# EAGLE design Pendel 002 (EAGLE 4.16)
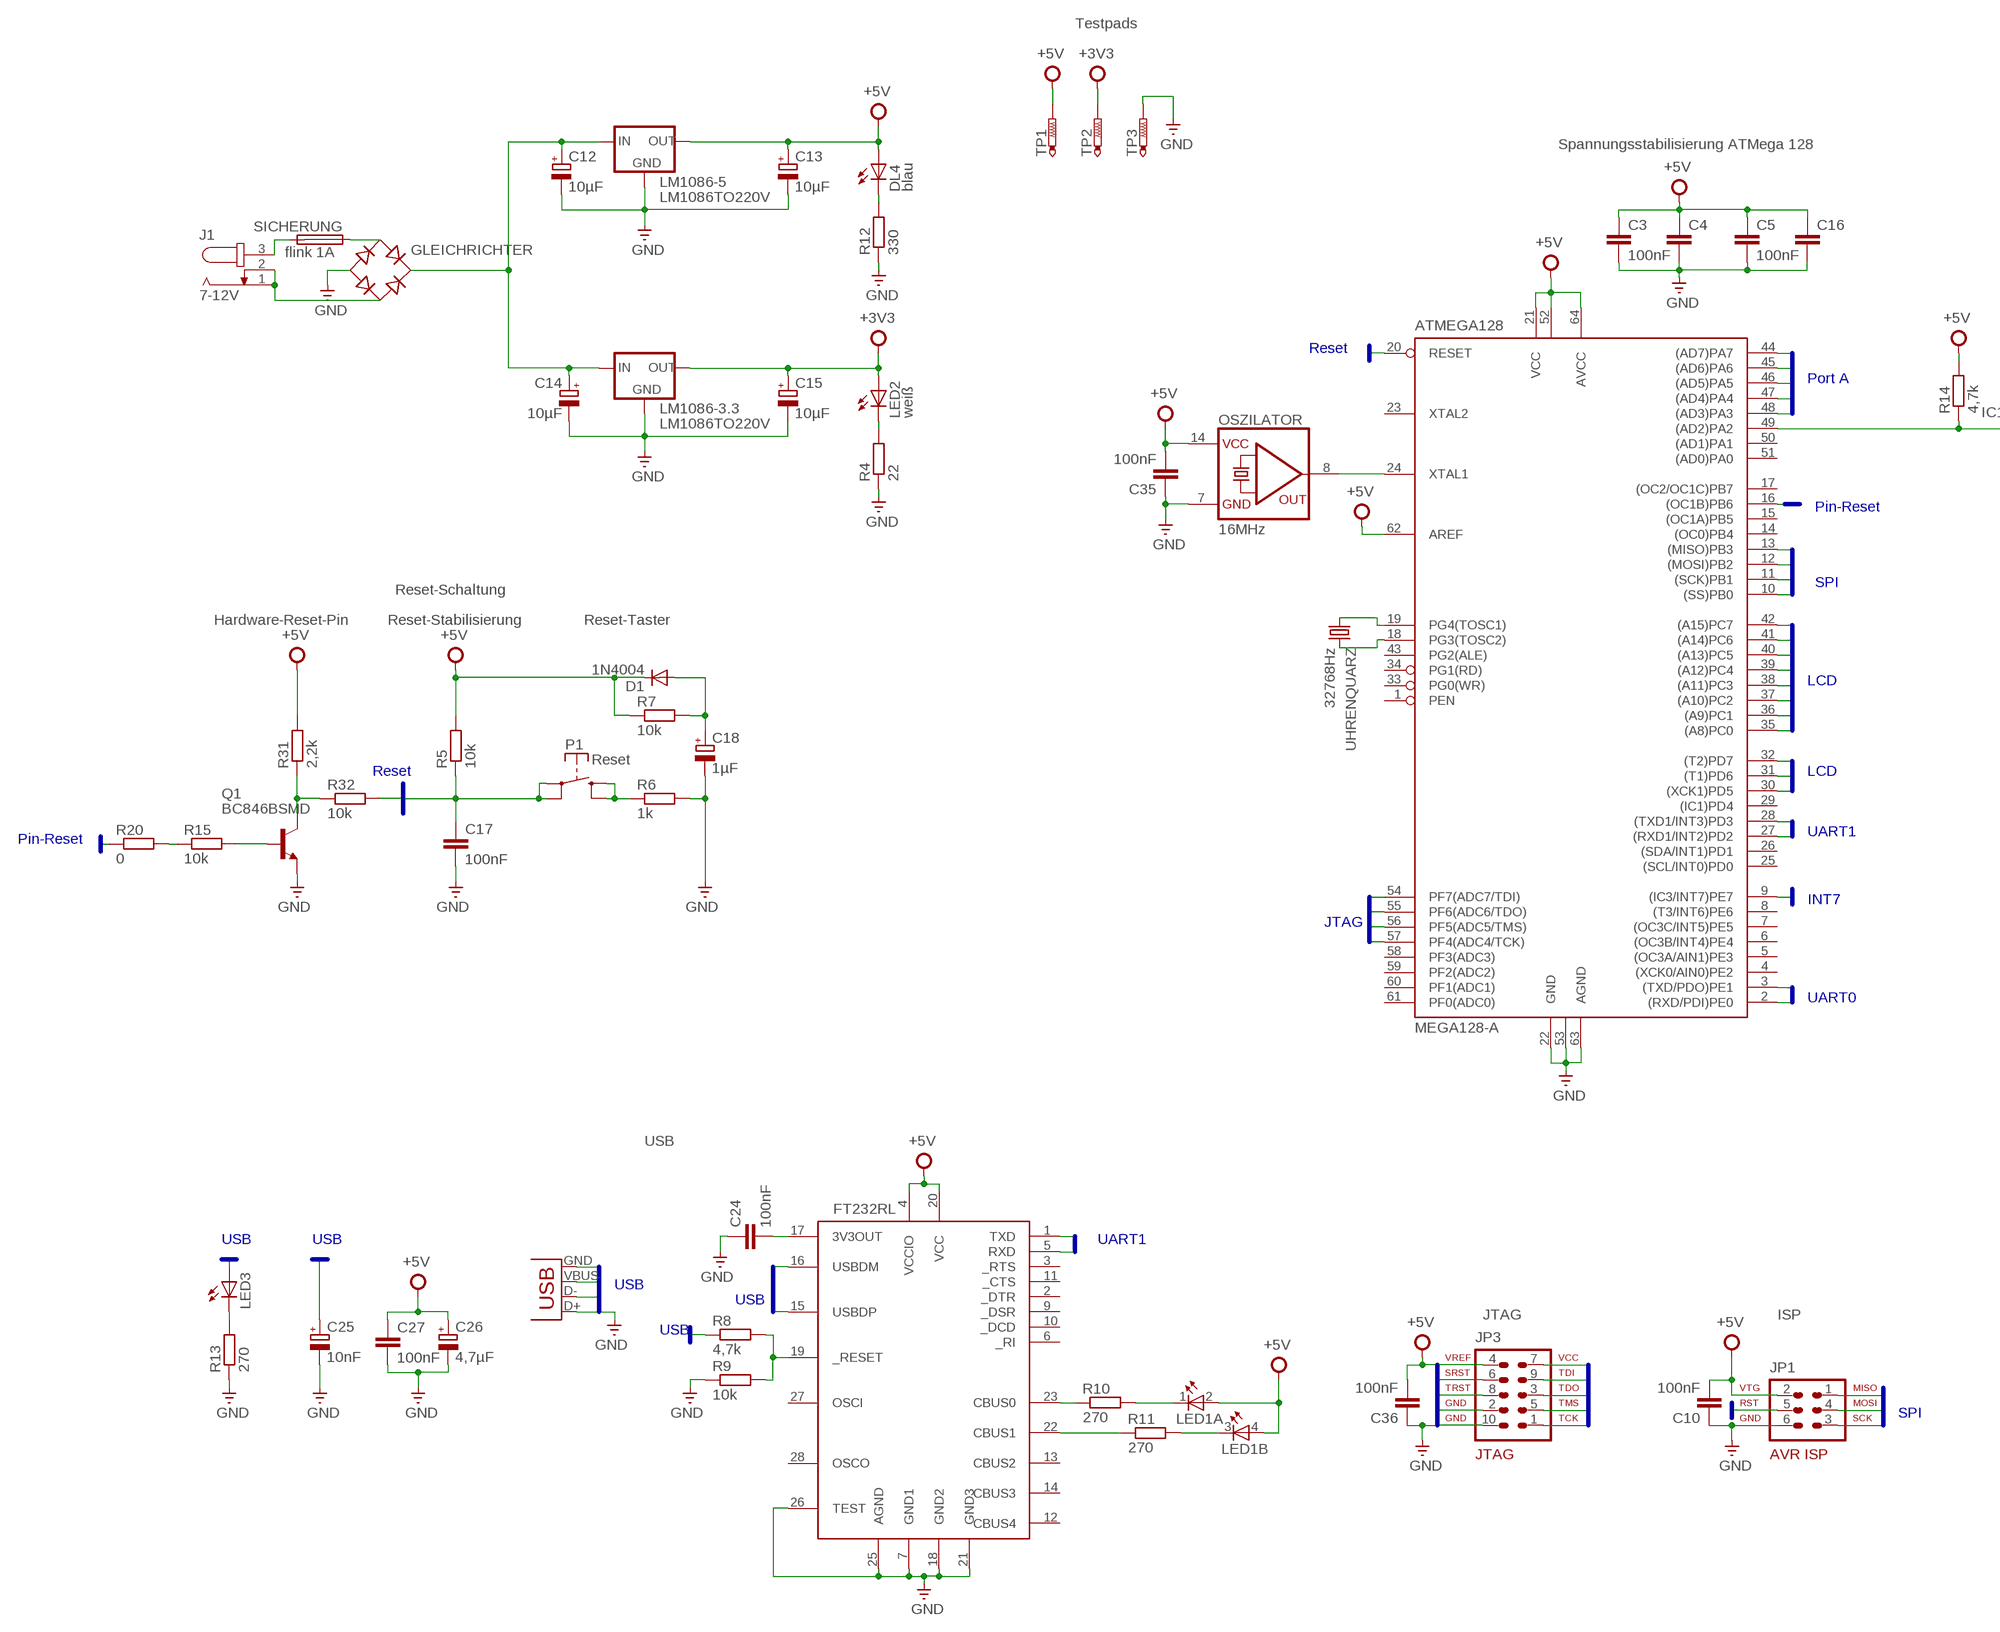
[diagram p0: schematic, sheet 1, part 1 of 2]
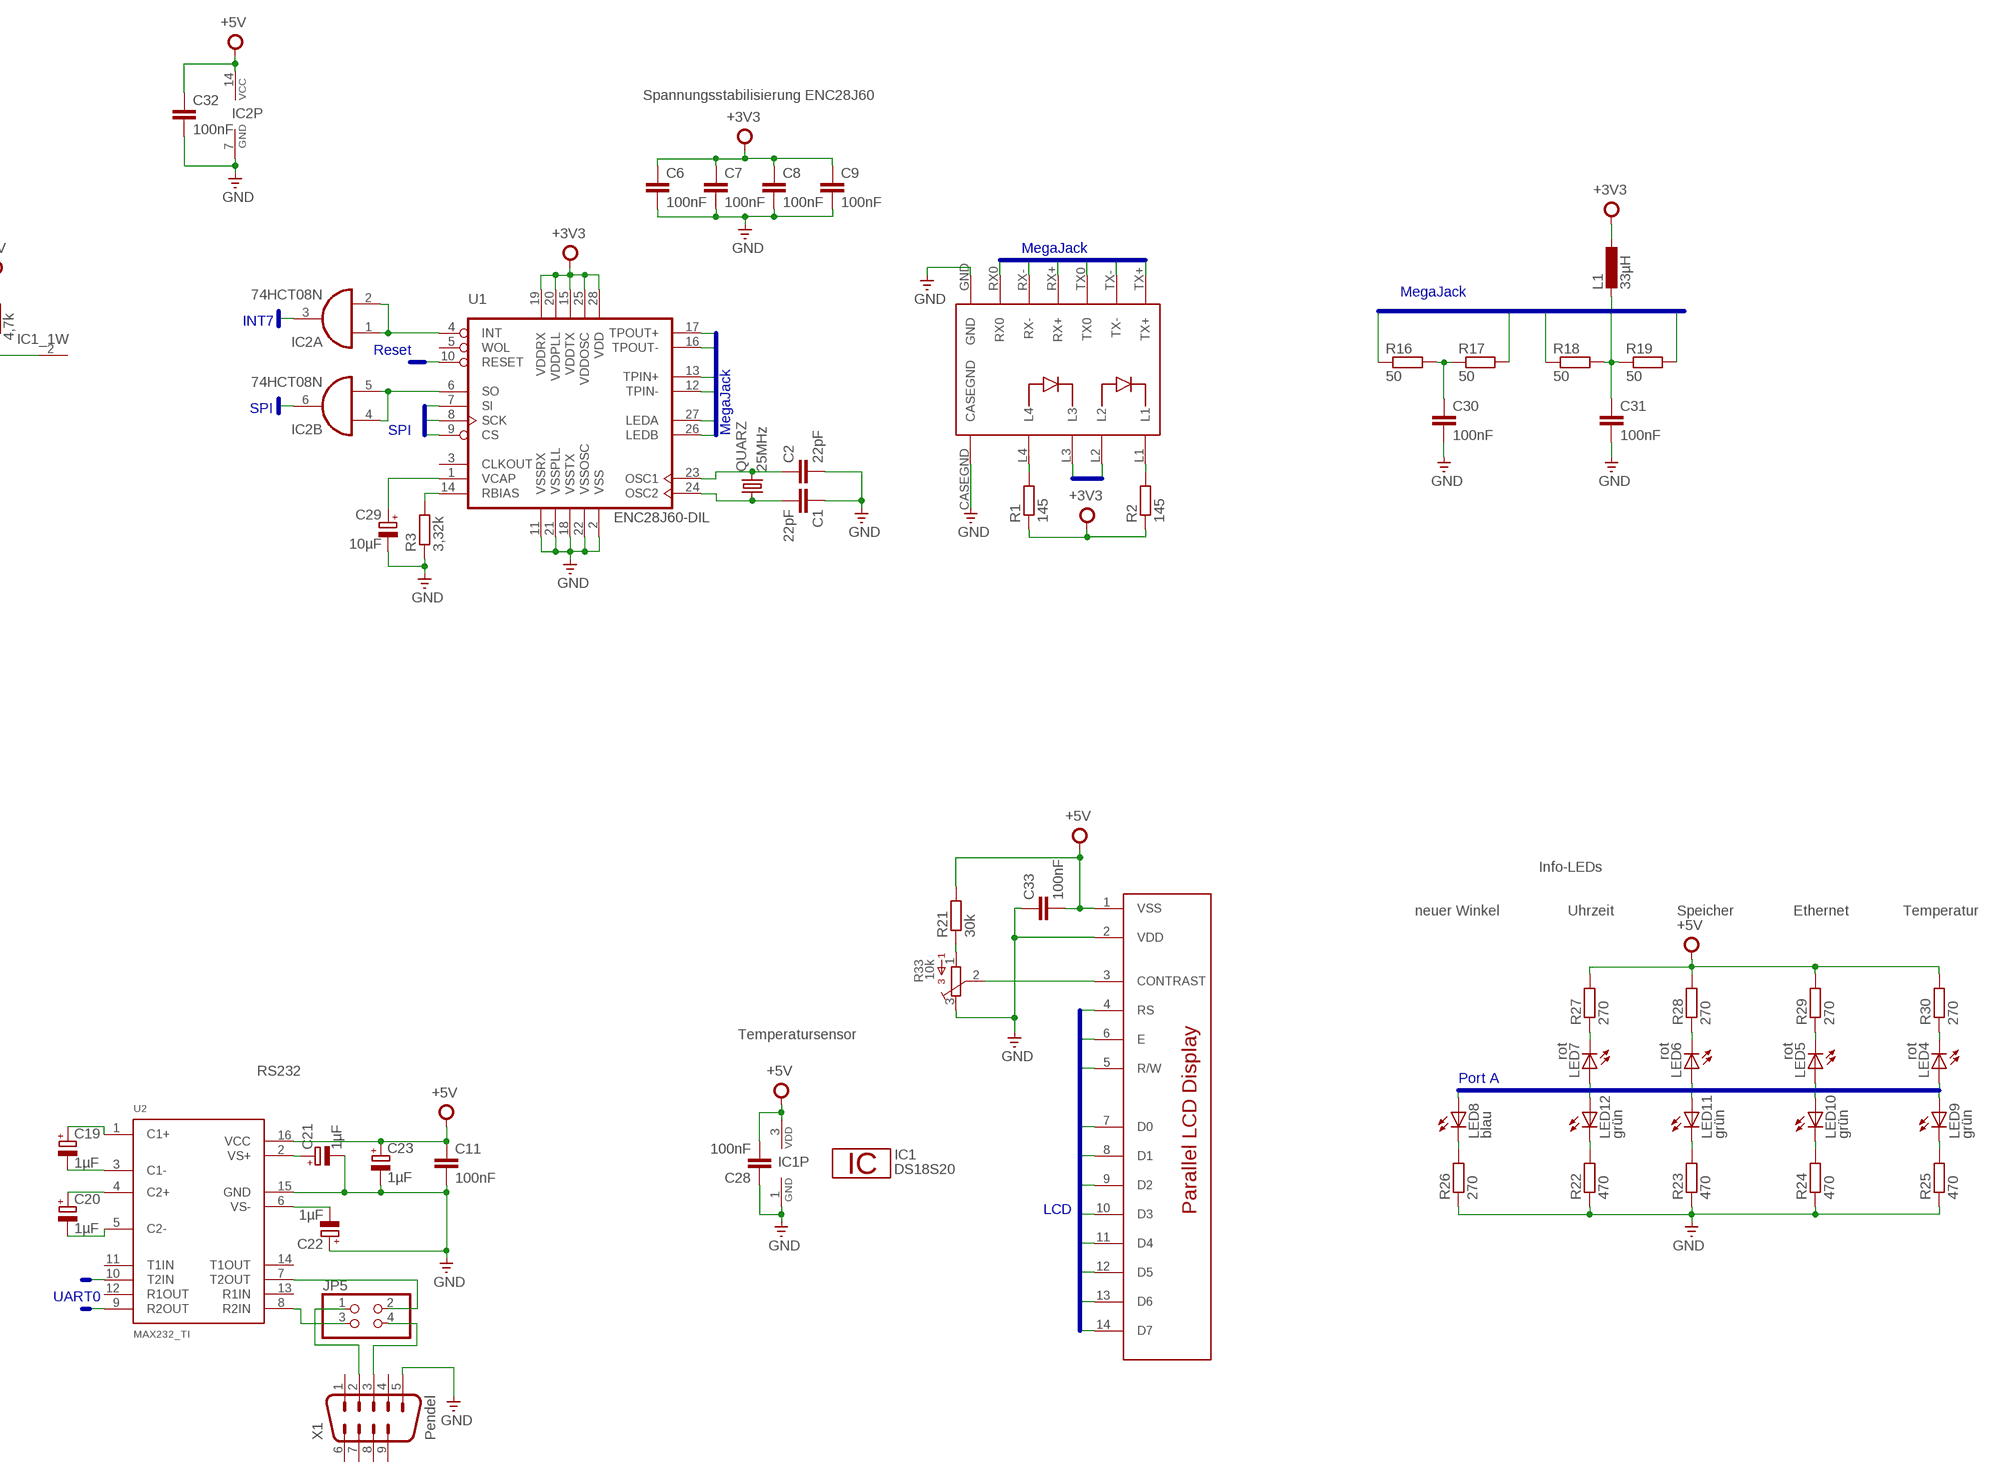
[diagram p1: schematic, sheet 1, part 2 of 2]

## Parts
ATMEGA128  MEGA128-A  [TQFP64-AEB]
C1  22pF  C-EUC1206  [C1206]
C2  22pF  C-EUC1206  [C1206]
C3  100nF  C-EUC0603  [C0603]
C4  C-EUC0603  [C0603]
C5  100nF  C-EUC0603  [C0603]
C6  100nF  C-EUC1206  [C1206]
C7  100nF  C-EUC1206  [C1206]
C8  100nF  C-EUC1206  [C1206]
C9  100nF  C-EUC1206  [C1206]
C10  100nF  C-EUC0805  [C0805]
C11  100nF  C-EUC1206  [C1206]
C12  10µF  CPOL-EUE2.5-6  [E2,5-6]
C13  10µF  CPOL-EUE2.5-6  [E2,5-6]
C14  10µF  CPOL-EUE2.5-6  [E2,5-6]
C15  10µF  CPOL-EUE2.5-6  [E2,5-6]
C16  C-EUC0603  [C0603]
C17  100nF  C-EUC1206  [C1206]
C18  1µF  CPOL-EUE2.5-6  [E2,5-6]
C19  1µF  CPOL-EUE2.5-6  [E2,5-6]
C20  1µF  CPOL-EUE2.5-6  [E2,5-6]
C21  1µF  CPOL-EUE2.5-6  [E2,5-6]
C22  1µF  CPOL-EUE2.5-6  [E2,5-6]
C23  1µF  CPOL-EUE2.5-6  [E2,5-6]
C24  100nF  C-EUC1206  [C1206]
C25  10nF  CPOL-EUE2.5-6  [E2,5-6]
C26  4,7µF  CPOL-EUE2.5-6  [E2,5-6]
C27  100nF  C-EUC1206  [C1206]
C28  100nF  C-EUC1206  [C1206]
C29  10µF  CPOL-EUE2.5-6  [E2,5-6]
C30  100nF  C-EUC1206  [C1206]
C31  100nF  C-EUC1206  [C1206]
C32  100nF  C-EUC1206  [C1206]
C33  100nF  C-EUC1206  [C1206]
C35  100nF  C-EUC1206  [C1206]
C36  100nF  C-EUC1206  [C1206]
D1  1N4004  [DO41-10]
DL4  blau  LEDCHIPLED_0603  [CHIPLED_0603]
FT232RL  FT232RL  [SSOP28DB]
GLEICHRICHTER  RB1A  [RB1A]
IC1  DS18S20  [TO92-]
IC2  74HCT08N  [DIL14]
J1  7-12V  JACK-PLUG0  [SPC4077]
JP1  AVR-ISP-6  [AVR-ISP-6]
JP3  AVR-JTAG-10  [AVR-JTAG-10]
JP5  PINHD-2X2_2.54  [2X02]
L1  33µH  L-EU2200-15.24  [2200-15.24]
LED1  TOPLED-2-/  [P-LCC-4/2]
LED2  weiß  LED5MM  [LED5MM]
LED3  LEDP-LCC-2  [P-LCC-2]
LED4  rot  LED5MM  [LED5MM]
LED5  rot  LED5MM  [LED5MM]
LED6  rot  LED5MM  [LED5MM]
LED7  rot  LED5MM  [LED5MM]
LED8  blau  LED5MM  [LED5MM]
LED9  grün  LED3MM  [LED3MM]
LED10  grün  LED3MM  [LED3MM]
LED11  grün  LED3MM  [LED3MM]
LED12  grün  LED3MM  [LED3MM]
LM1086-3.3  LM1086TO220V  [TO220S]
LM1086-5  LM1086TO220V  [TO220S]
OSZILATOR  16MHz  QG5860  [DIL14S]
P1  Reset  FSMCD  [FSMCD]
Q1  BC846BSMD  [SOT23]
QUARZ  25MHz  CRYTALHC49S  [HC49/S]
R1  145  R-EU_R1206  [R1206]
R2  145  R-EU_R1206  [R1206]
R3  3,32k  R-EU_R1206  [R1206]
R4  22  R-EU_R1206  [R1206]
R5  10k  R-EU_R1206  [R1206]
R6  1k  R-EU_R1206  [R1206]
R7  10k  R-EU_R1206  [R1206]
R8  4,7k  R-EU_R1206  [R1206]
R9  10k  R-EU_R1206  [R1206]
R10  270  R-EU_R1206  [R1206]
R11  270  R-EU_R1206  [R1206]
R12  330  R-EU_R1206  [R1206]
R13  270  R-EU_R1206  [R1206]
R14  4,7k  R-EU_R1206  [R1206]
R15  10k  R-EU_R1206  [R1206]
R16  50  R-EU_R1206  [R1206]
R17  50  R-EU_R1206  [R1206]
R18  50  R-EU_R1206  [R1206]
R19  50  R-EU_R1206  [R1206]
R20  0  R-EU_R1206  [R1206]
R21  30k  R-EU_R1206  [R1206]
R22  470  R-EU_R1206  [R1206]
R23  470  R-EU_R1206  [R1206]
R24  470  R-EU_R1206  [R1206]
R25  470  R-EU_R1206  [R1206]
R26  270  R-EU_R1206  [R1206]
R27  270  R-EU_R1206  [R1206]
R28  270  R-EU_R1206  [R1206]
R29  270  R-EU_R1206  [R1206]
R30  270  R-EU_R1206  [R1206]
R31  2,2k  R-EU_R1206  [R1206]
R32  10k  R-EU_R1206  [R1206]
R33  10k  3386-G  [3386G]
SICHERUNG  flink 1A  SH22,5A  [SH22,5A]
TP1  PTR1PAD1-13Y  [P1-13Y]
TP2  PTR1PAD1-13Y  [P1-13Y]
TP3  PTR1PAD1-13Y  [P1-13Y]
U1  ENC28J60-DIL  [DIL28-3]
U2  MAX232_TI  [DIL16]
U$2  PARALLEL_LCDDIP  [DIP_14]
U$3  1XRJ45_MM_JACK  [1XRJ45_MM_JACK]
UHRENQUARZ  32768Hz  CRYTALTC38H  [TC38H]
X1  Pendel  M09H  [M09H]
X2  USB-B-H  [USB-B-H]

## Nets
+3V3: C6.1 C7.1 C8.1 C9.1 C15.+ L1.1 LED2.A LM1086-3.3.2(OUT) R1.1 R2.1 TP2.1(TP) U1.15(VDDTX) U1.19(VDDRX) U1.20(VDDPLL) U1.25(VDDOSC) U1.28(VDD)
+5V: ATMEGA128.21(VCC) ATMEGA128.52(VCC1) ATMEGA128.62(AREF) ATMEGA128.64(AVCC) C3.1 C4.1 C5.1 C10.2 C11.1 C13.+ C16.1 C23.+ C26.+ C27.1 C28.2 C32.1 C33.2 C35.2 C36.2 D1.C DL4.A FT232RL.4(VCCIO) FT232RL.20(VCC) IC1.3 IC2.14(P:VCC) JP1.2 JP3.7 LED1.2(A:A) LED1.4(B:A) LM1086-5.2(OUT) OSZILATOR.14(VCC) R5.2 R7.1 R14.2 R21.2 R27.2 R28.2 R29.2 R30.2 R31.2 TP1.1(TP) U2.16(VCC) U$2.1(VSS)
D0: ATMEGA128.35((A8)PC0) U$2.7(D0)
D1: ATMEGA128.36((A9)PC1) U$2.8(D1)
D2: ATMEGA128.37((A10)PC2) U$2.9(D2)
D3: ATMEGA128.38((A11)PC3) U$2.10(D3)
D4: ATMEGA128.39((A12)PC4) U$2.11(D4)
D5: ATMEGA128.40((A13)PC5) U$2.12(D5)
D6: ATMEGA128.41((A14)PC6) U$2.13(D6)
D7: ATMEGA128.42((A15)PC7) U$2.14(D7)
D+: FT232RL.15(USBDP) X2.D+
D-: FT232RL.16(USBDM) X2.D-
E: ATMEGA128.32((T2)PD7) U$2.6(E)
GND: ATMEGA128.22(GND) ATMEGA128.53(GND1) ATMEGA128.63(AGND) C1.1 C2.2 C3.2 C4.2 C5.2 C6.2 C7.2 C8.2 C9.2 C10.1 C11.2 C12.- C13.- C14.- C15.- C16.2 C17.2 C18.- C21.- C22.+ C23.- C24.1 C25.- C26.- C27.2 C28.1 C29.- C30.2 C31.2 C32.2 C33.1 C35.1 C36.1 FT232RL.7(GND1) FT232RL.18(GND2) FT232RL.21(GND3) FT232RL.25(AGND) FT232RL.26(TEST) GLEICHRICHTER.- IC1.1 IC2.7(P:GND) JP1.6 JP3.2 JP3.10 LM1086-3.3.1(GND) LM1086-5.1(GND) OSZILATOR.7(GND) Q1.2(E) R3.1 R4.1 R6.2 R9.1 R12.1 R13.1 R22.1 R23.1 R24.1 R25.1 R26.1 R33.3 TP3.1(TP) U1.2(VSS) U1.11(VSSRX) U1.18(VSSTX) U1.21(VSSPLL) U1.22(VSSOSC) U2.15(GND) U$2.2(VDD) U$3.CASEGND U$3.GND X1.5 X2.GND
INT7: ATMEGA128.9((IC3/INT7)PE7) IC2.3(A:O)
L2: U1.26(LEDB) U$3.L2
L3: U1.27(LEDA) U$3.L3
MISO: ATMEGA128.13((MISO)PB3) IC2.6(B:O) JP1.1
MOSI: ATMEGA128.12((MOSI)PB2) JP1.4 U1.7(SI)
N$1: ATMEGA128.19(PG4(TOSC1)) UHRENQUARZ.1
N$2: ATMEGA128.18(PG3(TOSC2)) UHRENQUARZ.2
N$3: ATMEGA128.24(XTAL1) OSZILATOR.8(OUT)
N$4: R3.2 U1.14(RBIAS)
N$5: JP5.2 U2.7(T2OUT)
N$6: JP5.3 U2.8(R2IN)
N$7: C12.+ C14.+ GLEICHRICHTER.+ LM1086-3.3.3(IN) LM1086-5.3(IN)
N$8: C2.1 QUARZ.2 U1.23(OSC1)
N$9: C1.2 QUARZ.1 U1.24(OSC2)
N$10: LED2.K(C) R4.2
N$11: P1.P$3(S) P1.P$4(S) R6.1
N$12: C18.+ D1.A R7.2
N$13: C19.- U2.3(C1-)
N$14: C19.+ U2.1(C1+)
N$15: C20.+ U2.4(C2+)
N$16: C20.- U2.5(C2-)
N$17: C21.+ U2.2(VS+)
N$18: C22.- U2.6(VS-)
N$19: LED1.1(A:C) R10.2
N$20: R1.2 U$3.L4
N$21: R2.2 U$3.L1
N$22: DL4.C R12.2
N$23: LED3.C R13.2
N$24: FT232RL.19(_RESET) R8.2 R9.2
N$25: C24.2 FT232RL.17(3V3OUT)
N$26: FT232RL.23(CBUS0) R10.1
N$27: FT232RL.22(CBUS1) R11.1
N$28: C29.+ U1.1(VCAP)
N$29: LED1.3(B:C) R11.2
N$30: C30.1 R16.2 R17.1
N$31: ATMEGA128.49((AD2)PA2) IC1.2 R14.1
N$32: IC2.1(A:I0) IC2.2(A:I1) U1.4(INT)
N$33: IC2.4(B:I0) IC2.5(B:I1) U1.6(SO)
N$34: R33.2 U$2.3(CONTRAST)
N$35: R21.1 R33.1
N$36: JP5.4 X1.3
N$37: J1.3 SICHERUNG.2
N$38: JP5.1 X1.2
N$39: GLEICHRICHTER.AC2 J1.1 J1.2
N$45: R15.1 R20.2
N$46: GLEICHRICHTER.AC1 SICHERUNG.1
N$52: LED8.K(C) R26.2
N$53: LED12.K(C) R22.2
N$54: LED11.K(C) R23.2
N$55: LED7.K(C) R27.1
N$56: LED6.K(C) R28.1
N$57: LED5.K(C) R29.1
N$58: LED4.K(C) R30.1
N$59: LED9.K(C) R25.2
N$60: LED10.K(C) R24.2
N$61: Q1.1(B) R15.2
N$62: Q1.3(C) R31.1 R32.1
PORTA3: ATMEGA128.48((AD3)PA3) LED4.A LED9.A
PORTA4: ATMEGA128.47((AD4)PA4) LED5.A LED10.A
PORTA5: ATMEGA128.46((AD5)PA5) LED6.A LED11.A
PORTA6: ATMEGA128.45((AD6)PA6) LED7.A LED12.A
PORTA7: ATMEGA128.44((AD7)PA7) LED8.A
PORTB6: ATMEGA128.16((OC1B)PB6) R20.1
RESET: ATMEGA128.20(RESET) C17.1 JP1.5 P1.P$1(P) P1.P$2(P) R5.1 R32.2 U1.10(RESET)
RS: ATMEGA128.30((XCK1)PD5) U$2.4(RS)
RW: ATMEGA128.31((T1)PD6) U$2.5(R/W)
RX0: U$3.RX0
RX+: R17.2 U1.13(TPIN+) U$3.RX+
RX-: R16.1 U1.12(TPIN-) U$3.RX-
RXD0: ATMEGA128.2((RXD/PDI)PE0) U2.9(R2OUT)
RXD1: ATMEGA128.27((RXD1/INT2)PD2) FT232RL.1(TXD)
SCK: ATMEGA128.11((SCK)PB1) JP1.3 U1.8(SCK)
SRST: JP3.6
SS: ATMEGA128.10((SS)PB0) U1.9(CS)
TCK: ATMEGA128.57(PF4(ADC4/TCK)) JP3.1
TDI: ATMEGA128.54(PF7(ADC7/TDI)) JP3.9
TDO: ATMEGA128.55(PF6(ADC6/TDO)) JP3.3
TMS: ATMEGA128.56(PF5(ADC5/TMS)) JP3.5
TRST: JP3.8
TX0: C31.1 L1.2 R18.2 R19.1 U$3.TX0
TX+: R19.2 U1.17(TPOUT+) U$3.TX+
TX-: R18.1 U1.16(TPOUT-) U$3.TX-
TXD0: ATMEGA128.3((TXD/PDO)PE1) U2.10(T2IN)
TXD1: ATMEGA128.28((TXD1/INT3)PD3) FT232RL.5(RXD)
VBUS: C25.+ LED3.A R8.1 X2.VBUS
VREF: JP3.4
Unconnected: ATMEGA128.1(PEN) ATMEGA128.4((XCK0/AIN0)PE2) ATMEGA128.5((OC3A/AIN1)PE3) ATMEGA128.6((OC3B/INT4)PE4) ATMEGA128.7((OC3C/INT5)PE5) ATMEGA128.8((T3/INT6)PE6) ATMEGA128.14((OC0)PB4) ATMEGA128.15((OC1A)PB5) ATMEGA128.17((OC2/OC1C)PB7) ATMEGA128.23(XTAL2) ATMEGA128.25((SCL/INT0)PD0) ATMEGA128.26((SDA/INT1)PD1) ATMEGA128.29((IC1)PD4) ATMEGA128.33(PG0(WR)) ATMEGA128.34(PG1(RD)) ATMEGA128.43(PG2(ALE)) ATMEGA128.50((AD1)PA1) ATMEGA128.51((AD0)PA0) ATMEGA128.58(PF3(ADC3)) ATMEGA128.59(PF2(ADC2)) ATMEGA128.60(PF1(ADC1)) ATMEGA128.61(PF0(ADC0)) FT232RL.2(_DTR) FT232RL.3(_RTS) FT232RL.6(_RI) FT232RL.9(_DSR) FT232RL.10(_DCD) FT232RL.11(_CTS) FT232RL.12(CBUS4) FT232RL.13(CBUS2) FT232RL.14(CBUS3) FT232RL.27(OSCI) FT232RL.28(OSCO) IC2.8(C:O) IC2.9(C:I0) IC2.10(C:I1) IC2.11(D:O) IC2.12(D:I0) IC2.13(D:I1) U1.3(CLKOUT) U1.5(WOL) U2.11(T1IN) U2.12(R1OUT) U2.13(R1IN) U2.14(T1OUT) X1.1 X1.4 X1.6 X1.7 X1.8 X1.9

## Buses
MEGAJACK:RX-,RX+,RX0,TX-,TX+,TX0,L1,L2,L3,L4,GND,CASEGND
SPI:MISO,MOSI,SCK,SS
RESET
UART0:TXD0,RXD0
UART1:TXD1,RXD1
USB:D+,D-,GND,VBUS
INT7
LCD:RS,E,RW,D[0..7]
JTAG:VREF,SRST,TRST,+5V,GND,TDI,TDO,TMS,TCK
PORTA[0..7]
PORTB6

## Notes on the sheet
- Testpads
- Spannungsstabilisierung ATMega 128
- Spannungsstabilisierung ENC28J60
- MegaJack
- Reset
- MegaJack
- Port A
- INT7
- Reset
- SPI
- Pin-Reset | SPI | MegaJack
- SPI
- Reset-Schaltung
- Hardware-Reset-Pin | Reset-Stabilisierung | Reset-Taster
- LCD
- Reset | LCD
- UART1
- Pin-Reset
- INT7
- JTAG
- Info-LEDs
- UART0
- neuer Winkel | Uhrzeit | Speicher | Ethernet | Temperatur
- Temperatursensor
- USB
- RS232
- Port A
- USB | USB | UART1
- USB
- USB
- JTAG | ISP | LCD
- USB
- UART0
- SPI

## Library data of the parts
ATMEGA128 = atmel:MEGA128: MICROCONTROLLER 128 Kbytes FLASH 4 Kbytes SRAM 4 Kbytes EEPROM DUAL USART 8-channel 10 bit ADC
C1-C11 C16 C17 C24 C27 C28 C30-C33 C35 C36 = rcl:C-EU: CAPACITOR, European symbol
C12-C15 C18-C23 C25 C26 C29 = rcl:CPOL-EU: POLARIZED CAPACITOR, European symbol
D1 = diode:1N4004: DIODE
DL4 LED2-LED12 = led:LED: LED
FT232RL = ftdichip:FT232RL: USB UART 4th Generation USB UART (USB <-> Serial) Controller
GLEICHRICHTER = rectifier:RB1A: RECTIFIER 1 A
IC1 = 1wire:DS18S20: High Precision Digital Thermometer This chip provides a onewire thermosensor with approx. 0.5°C accuracy.A programmable over/undertemperure alarm is available. Notes: Vdd must be applied for accurate measurements at low temperatures, as the parasite power circuit otherwise heats the sensor. If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
IC2 = 74xx-eu:74*08: Quad 2-input AND gate
J1 = con-jack:JACK-PLUG: DC POWER JACK Power Jack, DC, Right Angle, Through Hole, Rated 5A at 16VDC, PC Terminals Distributor: Farnell (www.Farnell.de) Drawing: 84N1161.pdf / 84N1162.pdf Manufacturer: SPC Technology (www.spctechnology.com) Type: SPC4077 / SPC 4078
JP1 = atmel:AVR-ISP-6: AVR ISP-6 Serial Programming Header
JP3 = atmel:AVR-JTAG-10: AVR JTAG Debug/Programming Header
JP5 = pinhead-1:PINHD-2X2: PIN HEADER
L1 = rcl:L-EU: INDUCTOR, European symbol
LED1 = led:TOPLED-2-: Multi TOPLED® (two color) LG T672, LP T672 LSY T67B LSW T67C LSY T675 LSY T676 LSG T677 LSG T770 Source: http://www.osram.convergy.de/
LM1086-3.3 LM1086-5 = v-reg-2:LM1086
OSZILATOR = crystal:QG5860: CRYSTAL RESONATOR
P1 = switch-misc:FSMCD: TYCO SWITCH
Q1 = transistor-npn:BC846*: NPN Transistor
QUARZ UHRENQUARZ = crystal:CRYTAL: CRYSTAL
R1-R32 = rcl:R-EU_: RESISTOR, European symbol
R33 = BOURNS:3386-: 3386 Series 3/8" Square Trimmer
SICHERUNG = fuse:SH22,5A: FUSE HOLDER
TP1-TP3 = testpad:PTR1: TEST PIN
U1 = microchip-enc28j60:ENC28J60-*: Microchip 10Mbit Eth. contoller with SPI interface
U2 = max232ti:MAX232_TI: MAX232, Texas Instruments Version
U$2 = lcd_parallel:PARALLEL_LCD: Parallel LCD Alphanumeric LCD's usually common characters x line are 20x4, 2x16
U$3 = con_conec:1XRJ45_MM_JACK
X1 = con-subd:M09: HARTING SUB-D
X2 = con-usb:USB: USB Connectors

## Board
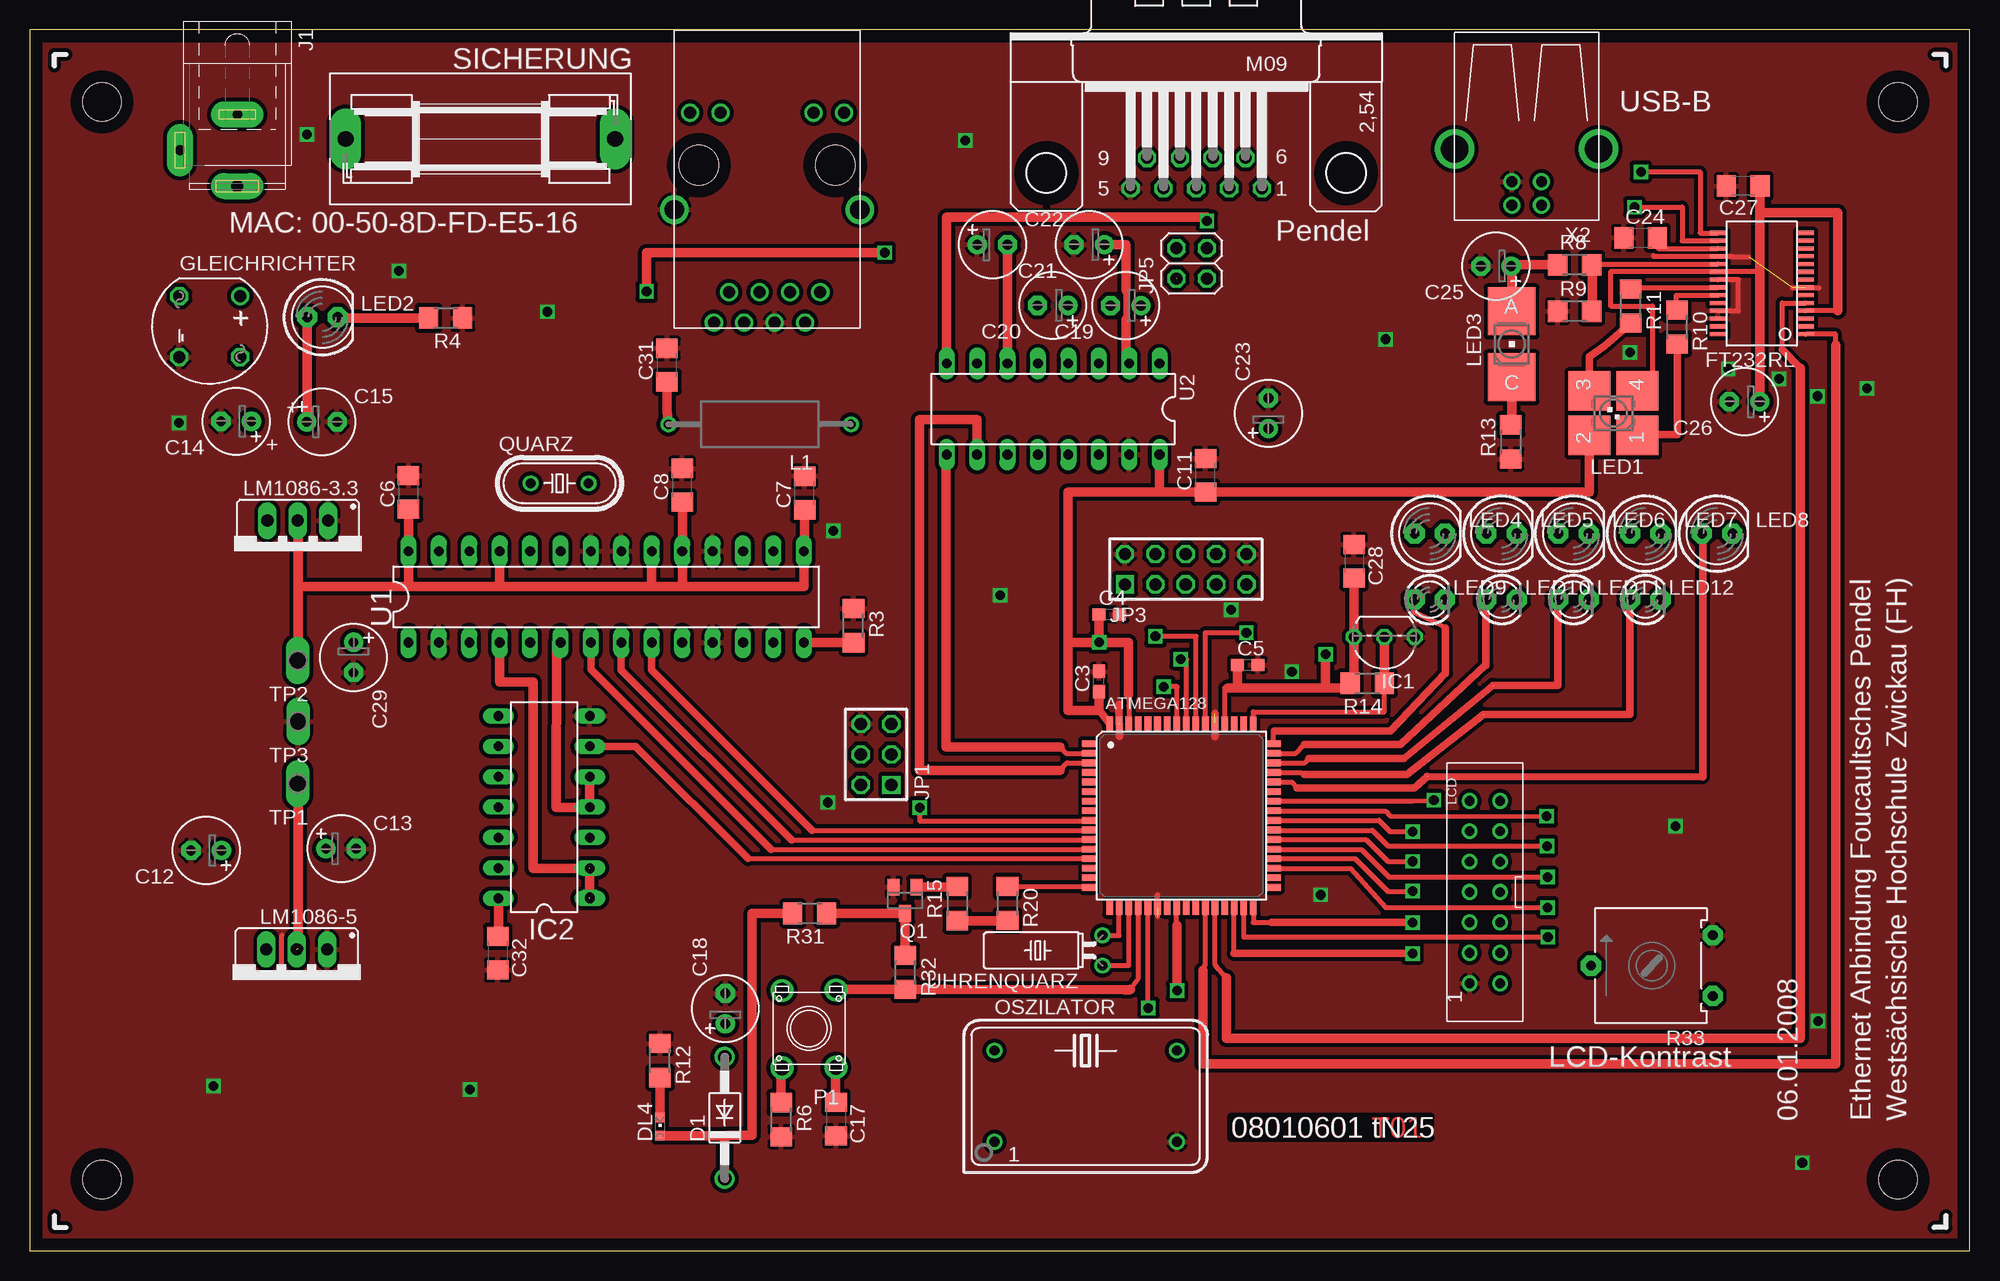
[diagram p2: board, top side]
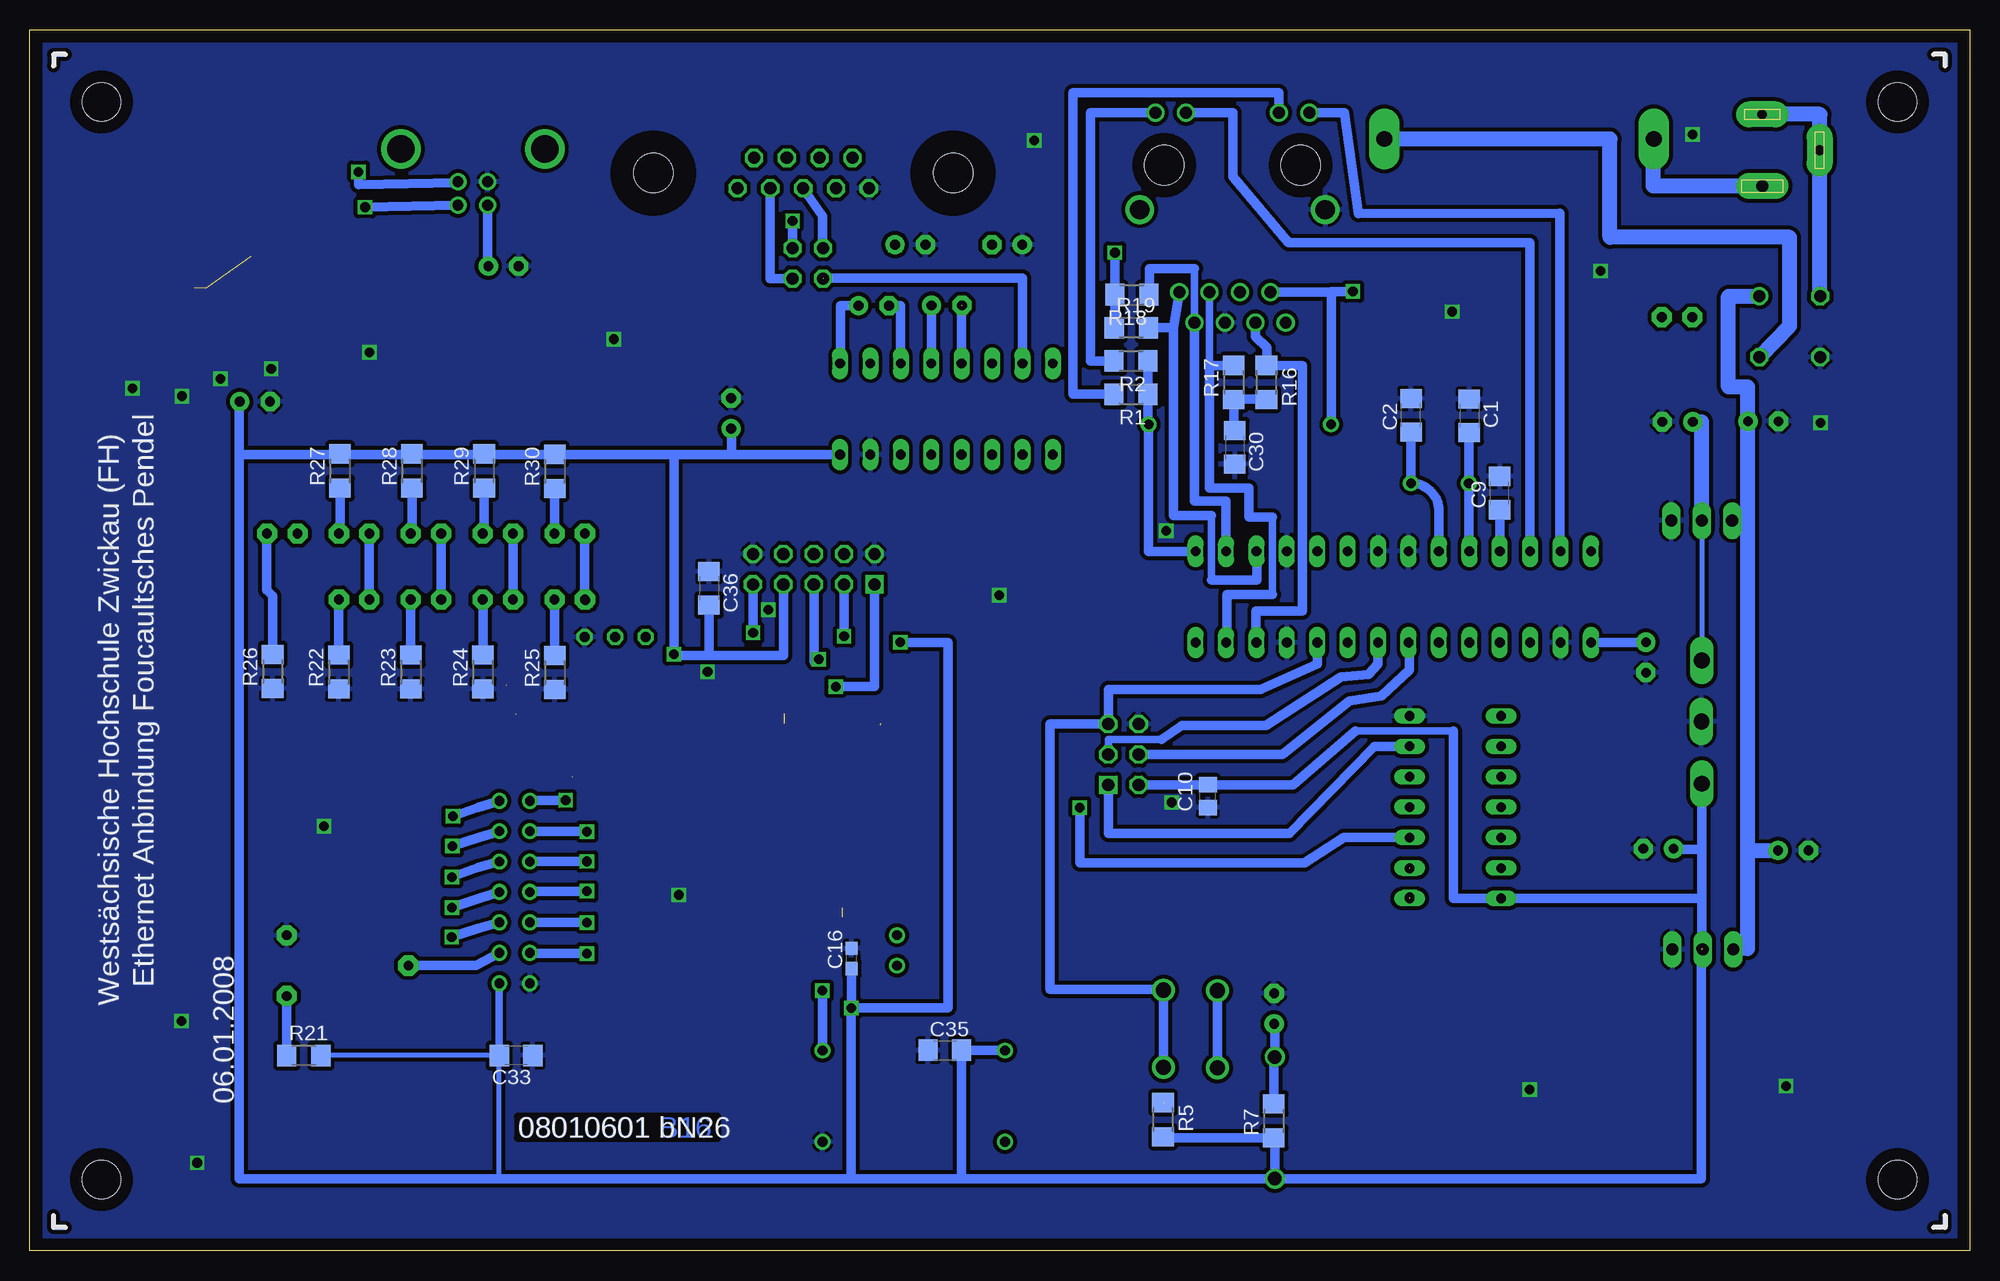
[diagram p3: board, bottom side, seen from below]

Size 162 x 102 mm. Coordinates in mm from the lower left corner, seen from the top.
Outline: 0,0 162,0 162,102 0,102 0,0
Copper layers (1*16): Top 0.035mm / dielectric 1.5mm / Bottom 0.035mm
Design rules "default": minimum track width 10mil, minimum drill 24mil, track to track 13mil, track to pad 13mil, pad to pad 13mil, via to via 13mil, smd to smd 13mil, copper to edge 40mil, drill to drill 8mil, minimum pad ring 10mil, minimum via ring 8mil, stop-mask expansion 4mil, vias tented up to drill 0mil, thermal gap 10mil
Holes 3.2 mm at 6.03,95.97 6.03,5.97 156.03,95.97 156.03,5.97

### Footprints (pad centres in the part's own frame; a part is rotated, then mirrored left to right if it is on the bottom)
TQFP64-AEB = smd 1.194 x 0.559: 1 -7.7,6; 2 -7.7,5.2; 3 -7.7,4.4; 4 -7.7,3.6; 5 -7.7,2.8; 6 -7.7,2; 7 -7.7,1.2; 8 -7.7,0.4; 9 -7.7,-0.4; 10 -7.7,-1.2; 11 -7.7,-2; 12 -7.7,-2.8; 13 -7.7,-3.6; 14 -7.7,-4.4; 15 -7.7,-5.2; 16 -7.7,-6; 33 7.7,-6; 34 7.7,-5.2; 35 7.7,-4.4; 36 7.7,-3.6; 37 7.7,-2.8; 38 7.7,-2; 39 7.7,-1.2; 40 7.7,-0.4; 41 7.7,0.4; 42 7.7,1.2; 43 7.7,2; 44 7.7,2.8; 45 7.7,3.6; 46 7.7,4.4; 47 7.7,5.2; 48 7.7,6 | smd 0.559 x 1.194: 17 -6,-7.7; 18 -5.2,-7.7; 19 -4.4,-7.7; 20 -3.6,-7.7; 21 -2.8,-7.7; 22 -2,-7.7; 23 -1.2,-7.7; 24 -0.4,-7.7; 25 0.4,-7.7; 26 1.2,-7.7; 27 2,-7.7; 28 2.8,-7.7; 29 3.6,-7.7; 30 4.4,-7.7; 31 5.2,-7.7; 32 6,-7.7; 49 6,7.7; 50 5.2,7.7; 51 4.4,7.7; 52 3.6,7.7; 53 2.8,7.7; 54 2,7.7; 55 1.2,7.7; 56 0.4,7.7; 57 -0.4,7.7; 58 -1.2,7.7; 59 -2,7.7; 60 -2.8,7.7; 61 -3.6,7.7; 62 -4.4,7.7; 63 -5.2,7.7; 64 -6,7.7
C1206 = smd 1.6 x 1.8: 1 -1.4,0; 2 1.4,0
C0603 = smd 1.1 x 1: 1 -0.85,0; 2 0.85,0
C0805 = smd 1.3 x 1.5: 1 -0.95,0; 2 0.95,0
E2,5-6 = drill 0.813 pad 1.6 round: + -1.27,0 | drill 0.813 pad 1.6 octagon: - 1.27,0
DO41-10 = drill 1.118 round: A 5.08,0; C -5.08,0
CHIPLED_0603 = smd 0.8 x 0.8: A 0,-0.75; C 0,0.75
SSOP28DB = smd 0.348 x 1.397: 1 -4.225,-3.656; 2 -3.575,-3.656; 3 -2.925,-3.656; 4 -2.275,-3.656; 5 -1.625,-3.656; 6 -0.975,-3.656; 7 -0.325,-3.656; 8 0.325,-3.656; 9 0.975,-3.656; 10 1.625,-3.656; 11 2.275,-3.656; 12 2.925,-3.656; 13 3.575,-3.656; 14 4.225,-3.656; 15 4.225,3.656; 16 3.575,3.656; 17 2.925,3.656; 18 2.275,3.656; 19 1.625,3.656; 20 0.975,3.656; 21 0.325,3.656; 22 -0.325,3.656; 23 -0.975,3.656; 24 -1.625,3.656; 25 -2.275,3.656; 26 -2.925,3.656; 27 -3.575,3.656; 28 -4.225,3.656
RB1A = drill 1.016 round: + -2.54,2.54 | drill 1.016 octagon: - 2.54,-2.54; AC1 2.54,2.54; AC2 -2.54,-2.54
TO92- = drill 0.813 octagon: 1 -2.54,0; 2 0,0; 3 2.54,0
DIL14 = drill 0.8 long: 1 -7.62,-3.81; 2 -5.08,-3.81; 3 -2.54,-3.81; 4 0,-3.81; 5 2.54,-3.81; 6 5.08,-3.81; 7 7.62,-3.81; 8 7.62,3.81; 9 5.08,3.81; 10 2.54,3.81; 11 0,3.81; 12 -2.54,3.81; 13 -5.08,3.81; 14 -7.62,3.81
SPC4077 = drill 0.8 pad 2.184 long: 1 -3,0; 2 0,-4.8 | drill 1 pad 2.184 long: 3 3,0
AVR-ISP-6 = drill 1.016 square: 1 -2.54,-1.27 | drill 1.016 octagon: 2 -2.54,1.27; 3 0,-1.27; 4 0,1.27; 5 2.54,-1.27; 6 2.54,1.27
AVR-JTAG-10 = drill 1.016 square: 1 -5.08,-1.27 | drill 1.016 octagon: 2 -5.08,1.27; 3 -2.54,-1.27; 4 -2.54,1.27; 5 0,-1.27; 6 0,1.27; 7 2.54,-1.27; 8 2.54,1.27; 9 5.08,-1.27; 10 5.08,1.27
2X02 = drill 1.016 octagon: 1 -1.27,-1.27; 2 -1.27,1.27; 3 1.27,-1.27; 4 1.27,1.27
2200-15.24 = drill 0.8 pad 1.27 round: 1 -7.62,0; 2 7.62,0
P-LCC-4/2 = smd 3.3 x 3.5: 1 -1.85,-2; 2 -1.85,2; 3 1.85,2; 4 1.85,-2
LED5MM = drill 0.813 pad 1.676 octagon: A -1.27,0; K 1.27,0
P-LCC-2 = smd 4 x 4: A 0,2.75; C 0,-2.75
LED3MM = drill 0.813 pad 1.676 octagon: A -1.27,0; K 1.27,0
TO220S = drill 1.016 long: 1 -2.54,-2.54; 2 0,-2.54; 3 2.54,-2.54
DIL14S = drill 0.813 round: 1 -7.62,-3.81; 7 7.62,-3.81; 8 7.62,3.81; 14 -7.62,3.81
FSMCD = drill 1.27 round: P$1 -2.25,3.25; P$2 -2.25,-3.2; P$3 2.25,3.3; P$4 2.25,-3.15
SOT23 = smd 1 x 1.4: 1 -0.95,-1.1; 2 0.95,-1.1; 3 0,1.1
HC49/S = drill 0.813 round: 1 -2.413,0; 2 2.413,0
R1206 = smd 1.6 x 1.803: 1 -1.422,0; 2 1.422,0
3386G = drill 0.813 pad 1.676 octagon: 1 -2.54,-5.08; 2 0,5.08; 3 2.54,-5.08
SH22,5A = drill 1.321 pad 2.54 long: 1 -11.252,0; 2 11.252,0
P1-13Y = drill 1.321 pad 1.905 long: 1 0,0
DIL28-3 = drill 0.813 long: 1 -16.51,-3.81; 2 -13.97,-3.81; 3 -11.43,-3.81; 4 -8.89,-3.81; 5 -6.35,-3.81; 6 -3.81,-3.81; 7 -1.27,-3.81; 8 1.27,-3.81; 9 3.81,-3.81; 10 6.35,-3.81; 11 8.89,-3.81; 12 11.43,-3.81; 13 13.97,-3.81; 14 16.51,-3.81; 15 16.51,3.81; 16 13.97,3.81; 17 11.43,3.81; 18 8.89,3.81; 19 6.35,3.81; 20 3.81,3.81; 21 1.27,3.81; 22 -1.27,3.81; 23 -3.81,3.81; 24 -6.35,3.81; 25 -8.89,3.81; 26 -11.43,3.81; 27 -13.97,3.81; 28 -16.51,3.81
DIL16 = drill 0.813 long: 1 -8.89,-3.81; 2 -6.35,-3.81; 3 -3.81,-3.81; 4 -1.27,-3.81; 5 1.27,-3.81; 6 3.81,-3.81; 7 6.35,-3.81; 8 8.89,-3.81; 9 8.89,3.81; 10 6.35,3.81; 11 3.81,3.81; 12 1.27,3.81; 13 -1.27,3.81; 14 -3.81,3.81; 15 -6.35,3.81; 16 -8.89,3.81
DIP_14 = drill 0.813 round: 1 7.62,1.27; 2 7.62,-1.27; 3 5.08,1.27; 4 5.08,-1.27; 5 2.54,1.27; 6 2.54,-1.27; 7 0,1.27; 8 0,-1.27; 9 -2.54,1.27; 10 -2.54,-1.27; 11 -5.08,1.27; 12 -5.08,-1.27; 13 -7.62,1.27; 14 -7.62,-1.27
1XRJ45_MM_JACK = drill 1.6 round: CASEGND -7.75,-3.7; P$2 7.75,-3.7 | drill 1 round: GND 0.635,-13.13; L1 6.44,4.38; L2 3.9,4.38; L3 -6.44,4.38; L4 -3.9,4.38; P$9 -0.635,-10.59; RX0 -4.445,-13.13; RX+ 1.905,-10.59; RX- -1.905,-13.13; TX0 -3.175,-10.59; TX+ 4.445,-10.59; TX- 3.175,-13.13 | hole 3.3: 5.7,0; -5.7,0
TC38H = drill 0.813 round: 1 -1.27,0; 2 1.27,0
M09H = drill 1.016 octagon: 1 5.486,-1.27; 2 2.743,-1.27; 3 0,-1.27; 4 -2.743,-1.27; 5 -5.486,-1.27; 6 4.115,1.27; 7 1.372,1.27; 8 -1.372,1.27; 9 -4.115,1.27 | hole 3.302: -12.522,0; 12.522,0
USB-B-H = drill 0.914 round: D+ 0,1.25; D- 1.981,1.25; GND 0,-1.25; VBUS 1.981,-1.25 | drill 2.286 round: P$1 -2.718,-6.02; P$2 -2.718,6.02

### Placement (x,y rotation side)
ATMEGA128  96.17,36.38 0 top
C1  41.79,69.78 270 bottom
C2  46.66,69.81 90 bottom
C3  89.28,47.57 90 top
C4  90.14,53.19 0 top
C5  101.72,48.96 0 top
C6  31.62,63.38 90 top
C7  64.7,63.31 90 top
C8  54.48,63.98 90 top
C9  39.25,63.31 90 bottom
C10  63.62,37.98 90 bottom
C11  98.19,64.8 90 top
C12  14.72,33.46 180 top
C13  25.98,33.6 0 top
C14  17.23,69.3 180 top
C15  24.39,69.27 0 top
C16  93.38,24.43 90 bottom
C17  67.33,11.02 270 top
C18  58.09,20.24 90 top
C19  91.53,78.97 180 top
C20  85.42,79 180 top
C21  88.47,84.06 180 top
C22  80.39,84.05 0 top
C23  103.44,69.97 90 top
C24  134.52,84.64 0 top
C25  122.45,82.28 180 top
C26  143.22,70.94 180 top
C27  143.09,88.97 180 top
C28  110.59,57.62 270 top
C29  27.03,49.59 270 top
C30  61.38,67.14 270 bottom
C31  53.2,74 90 top
C32  39.08,24.88 270 top
C33  121.39,16.32 180 bottom
C35  85.59,16.77 0 bottom
C36  105.28,55.37 270 bottom
D1  58.02,11.12 90 top
DL4  52.62,10.38 0 top
FT232RL  144.65,80.81 90 top
GLEICHRICHTER  15.01,77.22 270 top
IC1  113.12,51.3 180 top
IC2  42.95,37.07 90 top
J1  17.32,91.95 270 top
JP1  70.67,41.48 90 top
JP3  96.53,56.95 0 top
JP5  97.03,82.5 90 top
L1  60.95,69.06 180 top
LED1  132.25,69.98 90 top
LED2  24.43,78 0 top
LED3  123.75,75.75 0 top
LED4  116.92,59.92 0 top
LED5  122.92,59.92 0 top
LED6  128.92,59.92 0 top
LED7  134.93,59.92 0 top
LED8  140.93,59.92 0 top
LED9  116.92,54.42 0 top
LED10  122.92,54.42 0 top
LED11  128.92,54.42 0 top
LED12  134.93,54.42 0 top
LM1086-3.3  22.38,58.46 180 top
LM1086-5  22.28,22.66 180 top
OSZILATOR  88.17,12.93 0 top
P1  65.06,18.59 180 top
Q1  73.09,29.29 180 top
QUARZ  44.23,64.14 0 top
R1  70.05,71.58 180 bottom
R2  70.05,74.34 180 bottom
R3  68.78,52.23 270 top
R4  34.73,77.94 180 top
R5  67.36,10.98 270 bottom
R6  62.75,10.98 270 top
R7  58.11,10.88 90 bottom
R8  129.01,82.38 0 top
R9  129.01,78.5 0 top
R10  137.57,77.19 270 top
R11  133.71,78.94 270 top
R12  52.62,15.92 270 top
R13  123.69,67.58 90 top
R14  111.7,47.42 180 top
R15  77.45,29.02 90 top
R16  58.73,72.55 270 bottom
R17  61.45,72.55 90 bottom
R18  69.97,79.89 180 bottom
R19  70.02,77.11 0 bottom
R20  81.65,29.03 270 top
R21  139.12,16.32 0 bottom
R22  136.21,48.37 90 bottom
R23  130.19,48.37 90 bottom
R24  124.17,48.37 90 bottom
R25  118.17,48.32 90 bottom
R26  141.72,48.41 90 bottom
R27  136.1,65.16 90 bottom
R28  130.09,65.16 90 bottom
R29  124.06,65.16 90 bottom
R30  118.17,65.12 90 bottom
R31  65.12,28.2 180 top
R32  73.12,23.27 270 top
R33  135.47,23.84 90 top
SICHERUNG  37.63,92.89 180 top
TP1  22.37,39.03 180 top
TP2  22.38,49.34 180 top
TP3  22.39,44.23 180 top
U1  48.12,54.64 0 top
U2  85.45,70.33 180 top
U$2  121.52,29.98 270 top
U$3  61.56,90.69 0 top
UHRENQUARZ  89.59,25.11 90 top
X1  97.42,90.05 0 top
X2  125,89.33 270 top

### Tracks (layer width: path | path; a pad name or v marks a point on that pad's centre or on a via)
+3V3
  Top 0.254: U1.28 | U1.28 | U1.28 31.62,58.45
  Top 0.406: U1.15 64.63,58.39 64.7,58.39 | 54.51,62.57 C8.1 | 56.3,55.5 54.51,55.5 | 52.61,55.5 51.94,55.5 | 39.91,55.5 39.23,55.5 | 22.41,61.05 22.41,61 LM1086-3.3.2 | 23.12,69.25 23.11,69.25 | C15.+ 23.12,69.25 | 23.12,69.25 23.16,69.25 | 54.51,58.45 U1.19 54.51,58.45
  Top 0.813: 64.7,58.39 C7.1 | 54.51,58.45 54.51,62.57 | 64.63,58.39 64.63,55.5 56.3,55.5 52.61,55.5 39.91,55.5 31.62,55.5 | 54.51,55.5 54.51,58.45 | 51.94,55.5 U1.20 | 39.23,55.5 U1.25 | 31.62,55.5 U1.28 | 31.62,58.45 C6.1 | 22.41,55.5 31.62,55.5 | 22.41,55.5 22.41,61 | 23.16,69.25 LED2.A | 22.41,49.14 22.41,55.5
  Bottom 0.254: C9.1 39.15,61.55 39.23,61.55
  Bottom 0.406: 64.61,58.45 U1.15 | 68.61,74.34 R2.1 | 68.61,71.58 R1.1 | L1.1 68.61,69.06 | LM1086-3.3.2 22.38,61.05 | 22.38,61.05 TP2.1 | 22.38,61.05 22.41,61.05
  Bottom 0.813: L1.1 68.58,58.45 U1.15 | 68.61,74.34 68.61,71.58 68.61,69.06 | U1.25 39.23,61.55
  Bottom 1.27: C15.+ 23.12,69.25 22.38,69.25 LM1086-3.3.2
+5V  (via drill 0.8)  (2 unrouted)
  Top 0.406: LED1.2 129.75,68.19 | LED1.4 133.75,71.69 135.5,71.69 135.5,78.94 132,78.94 132,81.79 FT232RL.20 144.5,81.79 144.5,81.75 | 100.06,47.05 99.81,47.05 | 100.06,47.05 100.86,47.05 | ATMEGA128.52 99.78,47.05 100.06,47.05 | v22.41,25.24 22.3,25.24 | C32.1 39.08,26.34 39.13,26.34 | D1.C 58.01,6.04 | 58.01,9.63 57.61,9.63 57.61,9.65 58.2,9.65 58.11,9.65 | ATMEGA128.21 93.38,20.64 v93.41,20.3 | C26.+ 144.49,70.84 144.5,70.84 144.6,70.84 | 151,78.54 FT232RL.4 | 110.2,47.05 110.2,47.12 R14.2 110.27,47.14 | 110.27,47.14 110.2,47.14 | 110.27,47.14 110.59,47.14 | IC1.3 110.59,51.24 110.61,51.24 | 89.31,45.14 89.28,45.14 | ATMEGA128.62 91.78,45.53 91.77,46.45
  Top 0.61: 89.31,45.14 89.31,45.16 ATMEGA128.64
  Top 0.813: 100.86,47.05 C5.1 | v22.41,25.24 22.41,39.34 | 89.31,45.14 86.7,45.14 86.7,63.38 94.39,63.38 94.39,63.4 | IC2.14 39.13,26.34 | 57.61,9.63 DL4.A | 58.01,6.04 58.01,9.63 | 108.2,47.05 100.06,47.05 | v108.2,49.84 108.2,47.05 | 144.5,70.84 144.5,81.75 144.5,86.75 | 144.5,86.75 C27.1 | 151,78.54 151,86.75 144.5,86.75 | 108.2,47.05 110.2,47.05 | 110.59,47.14 IC1.3 | 110.59,51.24 C28.2 | R31.2 60.31,28.2 60.31,9.65 58.2,9.65 | 89.28,45.14 C3.1 | 91.77,46.45 91.77,50.84 v89.3,50.84 | v89.3,50.84 86.71,50.84 | 89.3,53.16 89.26,53.16 | 89.3,53.16 C4.1 | v89.3,50.84 89.3,53.16 | LED1.2 130.24,63.39 C11.1 94.34,63.39 | U2.16 94.34,63.39 | 94.39,63.4 94.58,63.4 | 94.34,63.39 94.34,63.4 94.39,63.4
  Bottom 0.406: LM1086-5.2 22.28,25.24 | IC2.14 | v22.41,25.24 22.41,29.45 22.41,33.55 | 24.71,33.55 C13.+ | 58.01,9.45 R7.1 | R5.2 67.41,9.55 67.41,9.45 | C33.2 122.81,16.34 | 122.81,22.36 U$2.1 | C33.2 | C33.2 R21.2 | 122.81,6.04 C33.2 | 132.1,66.53 132.41,66.53 132.41,66.55 R30.2 | 132.1,66.53 132,66.53 132.21,66.59 R28.2 | 144.5,66.44 144.5,66.53 | 103.41,66.53 103.41,66.5 | 103.41,68.7 C23.+ | 108.2,66.53 108.2,66.55 | 105.2,49.74 105.2,49.84 105.28,49.84 | v108.2,49.84 108.2,49.74 | v93.41,20.3 93.38,20.64 | OSZILATOR.14 80.61,16.73 80.61,16.77 | 84.2,6.04 84.19,6.04 | R29.2 129.1,66.59 129,66.53 | R27.2 132.31,66.59 132.1,66.53
  Bottom 0.61: 43.11,43.45 51.3,43.45 | JP1.2 | JP1.2 | C10.2 JP1.2 | C33.2 122.81,22.36
  Bottom 0.813: 22.37,25.24 TP1.1 | JP1.2 56.51,38.94 51.3,43.45 | 43.11,43.45 43.11,29.45 IC2.14 22.41,29.45 | 22.41,33.55 24.71,33.55 | v22.41,25.24 22.41,6.04 58.01,6.04 | 58.01,6.04 D1.C | 58.01,6.04 58.01,9.45 | R7.1 67.41,9.45 | 144.5,66.44 144.5,6.04 122.81,6.04 93.41,6.04 | 58.01,6.04 84.2,6.04 93.41,6.04 | 132.41,66.53 144.5,66.53 144.5,70.94 | 132,66.53 129,66.53 108.2,66.53 | 108.2,66.53 103.41,66.53 | 103.41,66.53 U2.16 | 103.41,66.53 103.41,68.7 | 108.2,66.53 v108.2,49.84 | JP3.7 99.08,49.74 105.2,49.74 108.2,49.74 | 105.28,49.84 C36.2 | 93.41,6.04 v93.41,20.3 85.34,20.3 85.34,50.84 v89.3,50.84 | 93.38,20.64 C16.1 | 80.61,16.77 C35.2 84.19,6.04
  Bottom 1.27: 144.5,70.94 C26.+
  other vias: 39.13,29.45
D0  (via drill 0.8)
  Top 0.406: ATMEGA128.35 103.91,31.95 110.31,31.95 113.23,28.7 v126.75,28.7
  Bottom 0.813: U$2.7 124.48,29.45 v126.75,28.7
D1  (via drill 0.8)
  Top 0.406: ATMEGA128.36 110.67,32.77 113.41,30.04 v115.48,30.04
  Bottom 0.813: U$2.8 120.2,29.98 120.2,30.04 v115.48,30.04
D2  (via drill 0.8)
  Top 0.406: ATMEGA128.37 103.91,33.55 111.2,33.55 113.5,31.24 v126.75,31.24
  Bottom 0.813: U$2.9 124.59,32.05 v126.75,31.24
D3  (via drill 0.8)
  Top 0.406: ATMEGA128.38 111.58,34.38 113.41,32.55 v115.48,32.55
  Bottom 0.813: U$2.10 120.22,32.52 120.2,32.55 v115.48,32.55
D4  (via drill 0.8)
  Top 0.406: ATMEGA128.39 103.91,35.14 112.11,35.14 113.41,33.84 v126.7,33.82
  Bottom 0.813: U$2.11 124.48,34.55 v126.7,33.82
D5  (via drill 0.8)
  Top 0.406: ATMEGA128.40 112.67,35.98 113.61,35.05 v115.48,35.05
  Bottom 0.813: U$2.12 120.22,35.06 120.2,35.05 v115.48,35.05
D6  (via drill 0.8)
  Top 0.406: ATMEGA128.41 103.91,36.74 113.2,36.74 113.61,36.34 v126.68,36.32
  Bottom 0.813: U$2.13 124.59,37.05 v126.68,36.32
D7  (via drill 0.8)
  Top 0.406: ATMEGA128.42 115.48,37.57 v117.26,37.64
  Bottom 0.813: U$2.14 120.2,37.6 120.2,37.64 v117.26,37.64
D+  (via drill 0.8)
  Top 0.406: FT232RL.15 139.5,85.04 139.5,90.14 v134.56,90.14 134.6,90.34
  Bottom 0.406: X2.D+ 126.25,89.25 | 134.53,90.14 v134.56,90.14
  Bottom 0.813: 126.25,89.25 134.53,89.07 134.53,90.14
D-  (via drill 0.8)
  Top 0.406: FT232RL.16 138,84.39 138,87.19 v134,87.19
  Bottom 0.406: 134.06,87.19 v134,87.19
  Bottom 0.813: X2.D- 134.06,87.19
E  (via drill 0.8)
  Top 0.406: 103.61,27.45 103.7,27.45 102.17,27.45 ATMEGA128.32
  Top 0.61: 103.7,27.45 v115.48,27.45
  Bottom 0.813: v115.48,27.45 U$2.6
GND  (via drill 0.8)  (5 unrouted)
  Top 0.406: FT232RL.21 142.21,81.14 142.71,81.14 142.71,78.55 141,78.55 141,78.54 FT232RL.25 | 135.6,83.14 135.6,83.09 FT232RL.18 142.21,83.09 142.21,83.05 143.56,83.05 | 90.97,45.64 90.91,45.64 | 94.18,27.92 94.18,29.77 | 147.23,80.47 149.43,80.47 | 21.03,23.77 21.03,26.37
  Top 0.61: ATMEGA128.63 90.97,45.64 | 90.98,42.97 90.98,43.94 | 98.98,42.99 98.98,44.89
  other vias: 107.81,29.74 67.11,60.14 105.41,48.39 133.63,75.07 12.43,69.17 15.33,13.77 36.73,13.47 137.43,35.47 153.43,72.07 148.03,7.37 113.23,76.17 81.03,54.77 23.13,93.27 30.83,81.87 43.23,78.47 66.63,37.47 100.33,53.57 149.36,19.2 149.29,71.41 141.85,73.68 146.09,72.84 78.13,92.77
  pour Bottom: 1.03,100.97 161.03,100.97 161.03,0.97 1.03,0.97
  pour Top: 1.03,100.97 162.93,100.97 162.93,-0.03 1.03,-0.03
INT7  (via drill 0.8)
  Top 0.406: 88.47,35.95 88.5,35.95 | 88.47,35.95 ATMEGA128.9 | v74.31,37.05 74.31,35.95 88.47,35.95
  Bottom 0.813: IC2.3 52.25,34.53 55.55,32.4 74.32,32.4 v74.31,37.05
L2
  Bottom 0.406: 36.7,58.45 U1.26
  Bottom 0.813: U$3.L2 61.51,95.08 61.51,89.75 56.91,84.25 36.7,84.25 36.7,58.45
L3
  Bottom 0.406: 34.2,58.45 U1.27
  Bottom 0.813: U$3.L3 52.23,95.08 51.03,86.67 34.2,86.67 34.2,58.45
MISO
  Top 0.406: 59.98,32.77 ATMEGA128.13 | 46.51,42.14 46.52,42.16 IC2.6
  Top 0.61: 59.98,32.77 50.61,42.14 46.51,42.14
  Bottom 0.406: 46.7,42.14 IC2.6
  Bottom 0.813: JP1.1 71.94,34.89 56.8,34.89 49.7,42.14 IC2.6
MOSI
  Top 0.406: ATMEGA128.12 88.5,33.55 61.91,33.55
  Top 0.61: U1.7 46.86,48.59 61.91,33.55
  Bottom 0.406: 46.8,50.84 U1.7
  Bottom 0.813: JP1.4 57.4,41.46 51.8,45.95 49.11,46.34 46.8,48.55 46.8,50.84
N$1
  Top 0.406: UHRENQUARZ.1 91.78,23.84 ATMEGA128.19
N$2
  Top 0.406: UHRENQUARZ.2 89.59,26.34 90.97,26.34 ATMEGA128.18
N$3  (via drill 0.8)
  Top 0.406: v95.81,21.74 95.78,21.74 | ATMEGA128.24 95.78,27.19
  Top 0.813: v95.81,21.74 v95.81,21.73 95.78,21.73 95.78,27.19
  Bottom 0.406: 95.8,17.34 95.81,17.34
  Bottom 0.813: OSZILATOR.8 95.8,17.34 | 95.81,17.34 v95.81,21.74
N$4
  Top 0.406: U1.14 64.63,50.84 | 68.78,50.84 R3.2
  Top 0.813: 64.63,50.84 68.78,50.84
N$5  (1 unrouted)
  Bottom 0.406: 95.73,81.16 95.75,81.25
  Bottom 0.61: 79.11,81.27 79.22,81.06 | 95.8,81.27 95.73,81.16
  Bottom 0.813: U2.7 79.11,81.27 95.8,81.27
N$6  (via drill 0.8)
  Top 0.813: U2.8 76.56,86.36 93.09,86.36 98.31,86.35 v98.31,86.05
  Bottom 0.406: 98.31,84.05 98.3,84.05
  Bottom 0.61: 98.29,83.75 98.3,83.75 JP5.3 | 98.31,84.05 98.31,83.75
  Bottom 0.813: v98.31,86.05 98.31,84.05 | 98.31,83.75 98.3,83.75
N$7
  Bottom 1.27: LM1086-3.3.3 19.8,61 | 19.8,25.2 LM1086-5.3 19.73,25.27 18.53,25.27 18.53,33.47 | LM1086-3.3.3 19.91,61 | GLEICHRICHTER.+ 20.13,79.75 20.13,72.17 18.53,72.17 18.53,69.3 | 18.53,69.3 C14.+ | 19.84,61.07 19.93,61.07 | 19.84,61.07 LM1086-3.3.3 | 18.53,61.07 18.53,69.3 | 18.53,61.07 19.84,61.07 | 18.53,33.47 18.53,61.07 | C12.+ 18.53,33.46 18.53,33.47
N$8
  Bottom 0.254: U1.23 arc90 U1.23
  Bottom 0.406: C2.1 46.66,68.44 46.65,68.44 46.61,68.44
  Bottom 0.813: U1.23 44.3,61.79 arc-90 QUARZ.2 46.65,68.44
N$9
  Bottom 0.254: U1.24 41.82,58.45
  Bottom 0.406: C1.2 41.79,68.25 41.82,68.25
  Bottom 0.813: 41.82,58.45 QUARZ.1 41.82,68.25
N$10
  Top 0.406: 25.71,77.94 25.71,78 LED2.K
  Top 0.813: 25.71,77.94 R4.2
N$11
  Top 0.406: P1.P$3 62.81,15.25 62.75,15.25
  Top 0.813: R6.1 62.75,15.25
  Bottom 0.406: P1.P$3 62.81,15.25 62.8,15.25
  Bottom 0.813: 62.81,15.25 P1.P$4
N$12
  Bottom 0.406: 58.02,16.14 58.01,16.14 | 58.02,16.14 D1.A | 58.11,16.14 58.02,16.14 | 58.09,18.95 58.11,18.95 | 58.09,18.95 C18.+ | 58.02,18.95 58.09,18.95
  Bottom 0.813: R7.2 58.11,16.14 | D1.A 58.02,18.95
N$13
  Bottom 0.406: U2.3 89.31,74.14
  Bottom 0.813: C19.- 89.31,78.97 89.31,74.14
N$14
  Bottom 0.406: U2.1 94.31,74.14
  Bottom 0.813: C19.+ 94.31,78.97 94.31,74.14
N$15
  Bottom 0.406: U2.4 86.7,74.14 | 86.7,79 C20.+
  Bottom 0.813: 86.7,74.14 86.7,79
N$16  (1 unrouted)
  Bottom 0.406: U2.5 84.2,74.14
  Bottom 0.813: 84.2,74.14 84.2,79
N$17  (via drill 0.8)
  Top 0.406: 91.53,77.82 91.53,80.26
  Top 0.813: U2.2 91.53,74.14 91.53,77.82 | 91.53,80.26 91.53,84.06 v89.75,84.06
  Bottom 0.813: C21.+ v89.75,84.06
N$18
  Top 0.406: U2.6 81.66,74.14 81.7,74.14
  Top 0.813: 81.66,74.14 C22.-
N$19
  Top 0.406: LED1.1 133.75,68.19
  Top 0.61: R10.2 137.57,68.19 133.75,68.19
N$20
  Bottom 0.813: U$3.L4 57.66,96.77 74.88,96.77 74.88,71.58 R1.2
N$21
  Bottom 0.813: U$3.L1 73.41,95.08 73.41,74.34 R2.2
N$22
  Top 0.406: R12.2 52.62,14.45 52.61,14.45
  Top 0.813: DL4.C 52.62,14.45
N$23
  Top 0.406: R13.2 123.69,69.14 123.75,69.14 123.86,69.14
  Top 0.813: 123.75,69.14 LED3.C
N$24
  Top 0.406: 130.5,82.44 130.5,82.38 R8.2 | 130.5,82.44 FT232RL.19 | 130.5,82.44 | R9.2 130.5,78.5
  Top 0.813: 130.5,78.5 130.5,82.38
N$25
  Top 0.406: C24.2 136,84.64 136,83.74 FT232RL.17
N$26
  Top 0.406: R10.1 137.5,78.61 137.5,79.84 FT232RL.23
N$27
  Top 0.406: 133.75,80.36 133.75,80.19 | R11.1 133.75,80.36 | FT232RL.22 133.75,80.49 133.75,80.36
N$28
  Bottom 0.406: 31.62,50.84 U1.1 | C29.+ 27.03,50.84
  Bottom 0.813: 27.03,50.84 31.62,50.84
N$29
  Top 0.61: R11.2 131.5,75.59 130.25,74.69 LED1.3
N$30
  Bottom 0.406: C30.1 61.45,68.55 | 58.7,71.14 58.73,71.14 R16.2 | R17.1 61.45,71.14
  Bottom 0.813: 61.45,68.55 R17.1 | 61.45,71.14 58.73,71.14
N$31
  Top 0.406: R14.1 113.12,45.05 102.17,45.05 ATMEGA128.49 | IC1.2 113.12,51.34 113.11,51.34
  Top 0.813: R14.1 113.12,51.34
N$32  (via drill 0.8)  (2 unrouted)
  Top 0.406: v46.76,29.54 46.8,29.54
  Top 0.813: U1.4 39.23,47.55 42.05,47.55 42.05,31.95 v46.76,31.95 v46.76,29.54
N$33
  Top 0.406: 46.61,37.05 46.55,37.05 IC2.4 46.76,37.05 46.91,37.05 | 43.97,50.87 44.03,50.84
  Top 0.813: 43.97,50.87 43.95,37.05 46.55,37.05 | 44.03,50.84 U1.6 | 46.76,37.05 IC2.5
N$34
  Bottom 0.813: 130.42,23.87 130.43,23.87 | 130.42,23.87 R33.2 | U$2.3 124.72,23.87 130.42,23.87
N$35
  Bottom 0.813: 140.55,21.27 R33.1 | R21.1 140.55,21.27 | 140.55,21.27 140.53,21.27
N$36
  Bottom 0.406: 97.5,88.84 97.44,88.78 X1.3
  Bottom 0.61: JP5.4 95.8,83.76
  Bottom 0.813: 97.44,88.78 95.8,86.42 95.8,83.76
N$37
  Bottom 1.27: SICHERUNG.2 26.43,92.89 26.43,88.95 J1.3
N$38
  Bottom 0.406: 100.2,88.78 X1.2
  Bottom 0.61: JP5.1
  Bottom 0.813: 100.2,88.78 100.2,81.22 JP5.1
N$39
  Bottom 1.27: GLEICHRICHTER.AC2 12.47,79.75 12.51,79.75 J1.2 | J1.2 | J1.1 12.5,94.95 J1.2
N$40
  Top 0.406: 159.03,1.97 160.03,1.97 160.03,2.97
N$41
  Bottom 0.406: 159.03,1.97 160.03,1.97 160.03,2.97
N$42
  Bottom 0.406: 3.03,99.97 2.03,99.97 2.03,98.97
N$43
  Top 0.406: 159.03,99.97 160.03,99.97 160.03,98.97
N$44
  Bottom 0.406: 159.03,99.97 160.03,99.97 160.03,98.97
N$45
  Top 0.813: R20.2 81.65,27.57 77.45,27.57 R15.1
N$46
  Bottom 1.27: SICHERUNG.1 30.03,92.89 30.03,84.67 15.03,84.67 15.03,77.27 17.53,74.67 GLEICHRICHTER.AC1
N$49
  Bottom 0.406: 2.03,2.97 2.03,1.97 3.03,1.97
N$50
  Top 0.406: 2.03,2.97 2.03,1.97 3.03,1.97
N$51
  Top 0.406: 3.03,99.97 2.03,99.97 2.03,98.97
N$52
  Bottom 0.406: 142.19,59.84 142.22,59.84 | 142.23,59.84 142.19,59.84 | 142.19,59.84 LED8.K
  Bottom 0.813: R26.2 141.72,54.71 142.23,55.22 142.23,59.84
N$53
  Bottom 0.406: 136.21,54.45 136.19,54.45 LED12.K
  Bottom 0.813: R22.2 136.21,54.45
N$54
  Bottom 0.406: 130.19,54.45 130.21,54.45 | 130.19,54.45 LED11.K | 130.19,54.45
  Bottom 0.813: R23.2 130.19,54.45
N$55
  Bottom 0.406: 136.19,59.95 136.21,59.95 | LED7.K 136.19,59.95 | 136.19,59.95 136.1,59.95
  Bottom 0.813: 136.1,59.95 R27.1
N$56
  Bottom 0.406: 130.19,59.95 130.21,59.95 | LED6.K 130.19,59.95 | 130.19,59.95 130.09,59.95
  Bottom 0.813: 130.09,59.95 R28.1
N$57
  Bottom 0.406: 124.2,59.95 | LED5.K 124.2,59.95 | 124.2,59.95 124.06,59.95
  Bottom 0.813: 124.06,59.95 R29.1
N$58
  Bottom 0.406: 118.2,59.95 | LED4.K 118.2,59.95 | 118.2,59.95 118.17,59.95
  Bottom 0.813: 118.17,59.95 R30.1
N$59
  Bottom 0.406: 118.2,54.45 | 118.2,54.45 LED9.K | 118.17,54.45 118.2,54.45
  Bottom 0.813: R25.2 118.17,54.45
N$60
  Bottom 0.406: 124.2,54.34 | 124.2,54.34 LED10.K | 124.17,54.34 124.2,54.34
  Bottom 0.813: R24.2 124.17,54.34
N$61
  Top 0.406: R15.2 77.41,30.45 77.41,30.39 77.41,30.34
  Top 0.813: Q1.1 77.41,30.39
N$62
  Top 0.406: R31.1 66.5,28.2 66.5,28.14 | R32.1 73.12,24.64 73.09,24.64
  Top 0.813: 66.5,28.2 Q1.3 73.09,24.64
PORTA3  (via drill 0.8)
  Top 0.406: v115.61,54.34 115.61,53.34 117.5,52.45 118.2,52.05 | ATMEGA128.48 103.88,43.51 103.95,43.44
  Top 0.61: 118.2,48.28 118.2,48.24 | 118.2,48.28 118.2,52.05 | 103.95,43.44 113.63,43.44 118.23,48.28 118.2,48.28
  Bottom 0.406: LED9.A 115.66,54.34 v115.61,54.34
  Bottom 0.813: 115.66,54.34 LED4.A
PORTA4
  Top 0.406: 121.61,54.45 121.64,54.45 LED10.A | ATMEGA128.47 105.72,41.57 106.46,42.31 | 121.53,48.9 121.64,48.91 121.61,48.91
  Top 0.61: 121.61,48.91 121.61,54.45 | 106.46,42.31 114.46,42.31 121.53,48.9
  Bottom 0.406: LED10.A 121.66,54.34 121.81,54.34
  Bottom 0.813: 121.66,54.34 LED5.A
PORTA5  (1 unrouted)
  Top 0.406: 127.61,54.45 127.61,54.42 LED11.A | ATMEGA128.46 106.47,40.77 106.83,41.13
  Top 0.61: 122.23,47.25 127.61,47.25 127.61,54.42 | 106.83,41.13 114.75,41.13 122.18,47.26
  Bottom 0.406: LED11.A 127.66,54.34 127.61,54.34
  Bottom 0.813: 127.66,54.34 LED6.A
PORTA6  (1 unrouted)
  Top 0.406: 133.6,54.42 LED12.A | ATMEGA128.45 106.17,39.98 106.46,39.8
  Top 0.61: 121.42,44.82 133.6,44.81 133.6,54.42 | 106.46,39.8 114.99,39.8 121.4,44.83
  Bottom 0.406: LED12.A 133.66,54.34 133.71,54.34
  Bottom 0.813: 133.66,54.34 LED7.A
PORTA7  (1 unrouted)
  Top 0.406: 139.71,59.92 LED8.A | ATMEGA128.44 105.36,39.17 105.84,38.7
  Top 0.61: 116.7,39.62 139.72,39.62 139.71,59.92 | 105.84,38.7 115.63,38.7 116.7,39.63
PORTB6
  Top 0.406: 81.65,30.47 81.63,30.47 | R20.1 81.65,30.47 | ATMEGA128.16 88.47,30.47 81.65,30.47
RESET  (1 unrouted)
  Top 0.406: 67.31,21.84 P1.P$2 | 91.91,21.84 92.58,22.79 92.57,22.79 92.57,24.16 ATMEGA128.20 | P1.P$1 | R32.2 76.81,21.84 | 67.31,12.35 67.41,12.35 67.41,12.42 C17.1 67.31,12.42 67.31,12.65 67.31,12.35 | 67,12.35 67.31,12.35
  Top 0.813: 67.31,21.84 76.81,21.84 91.4,21.83 91.81,21.83 91.91,21.84 | 67.31,12.65 P1.P$1
  Bottom 0.406: JP1.5 71.91,44.52 | 67.31,21.84 P1.P$2 | P1.P$1 | R5.1 67.31,12.4 67.31,12.95
  Bottom 0.813: U1.10 54.48,49.02 59.23,46.91 59.2,46.91 71.91,46.91 71.91,44.52 | JP1.5 76.81,44.02 76.81,21.84 67.31,21.84 | P1.P$1 P1.P$2
RS  (via drill 0.8)
  Top 0.406: 100.58,24.84 ATMEGA128.30
  Top 0.61: 100.58,24.84 v115.48,24.84
  Bottom 0.813: U$2.4 120.2,24.9 120.2,24.84 v115.48,24.84
RW  (via drill 0.8)
  Top 0.406: ATMEGA128.31 101.38,26.22 v126.78,26.22
  Bottom 0.813: U$2.5 124.59,26.95 v126.78,26.22
RX+
  Bottom 0.406: 63.44,63.74 63.41,63.74 63.47,63.74 | U1.13 62.01,50.84 | 61.45,73.94 R17.2
  Bottom 0.61: 58.25,54.84 58.25,61.32 | 63.47,73.94 U$3.RX+
  Bottom 0.813: 58.25,61.32 60.2,61.32 60.2,63.74 63.41,63.74 | 58.25,54.84 62.01,54.84 62.01,50.84 | 63.47,63.74 63.47,73.94 61.45,73.94
RX-
  Bottom 0.406: 59.61,50.84 U1.12 | 58.7,73.94 58.7,73.98 R16.1
  Bottom 0.813: 59.61,50.84 59.61,53.45 55.7,53.45 55.7,73.94 58.7,73.94 | U$3.RX- 59.66,76.4 58.7,75.44 58.7,73.98
RXD0
  Top 0.406: 76.5,66.55 76.5,66.53 U2.9 | ATMEGA128.2 86.55,41.57 86.02,42.12
  Top 0.813: 76.5,42.12 | 76.5,42.12 76.5,66.53 | 76.5,42.12 86.02,42.12
RXD1
  Top 0.406: FT232RL.1 150.81,76.59 150.81,75.68 | ATMEGA128.27 98.17,23.92 97.97,23.44
  Top 0.813: 97.97,23.44 97.97,15.62 150.81,15.62 150.81,75.68
SCK
  Top 0.406: ATMEGA128.11 88.5,34.34 63.61,34.34
  Top 0.61: U1.8 49.4,48.55 63.61,34.34
  Bottom 0.406: 49.41,50.84 U1.8
  Bottom 0.61: JP1.3 71.94,42.74 67.5,42.74
  Bottom 0.813: 67.5,42.74 65.78,43.88 58.77,43.89 52.51,47.95 50.2,48.14 49.41,49.05 49.41,50.84
SS
  Top 0.406: ATMEGA128.10 88.5,35.14 65.31,35.14
  Top 0.61: U1.9 51.94,48.52 65.31,35.14
TCK  (via drill 0.8)
  Top 0.406: 95.81,44.07 95.81,44.05 | ATMEGA128.57 95.81,44.07 | v94.7,47.14 95.81,47.14 95.81,44.07
  Bottom 0.813: JP3.1 91.45,47.14 v94.7,47.14
TDI  (via drill 0.8)
  Top 0.406: ATMEGA128.54 98.17,51.64 v101.61,51.64
  Bottom 0.406: 101.61,55.64 JP3.9
  Bottom 0.813: v101.61,51.64 101.61,55.64
TDO  (via drill 0.8)
  Top 0.406: ATMEGA128.55 97.38,45.64 97.41,45.64 97.41,51.34 v94,51.34
  Bottom 0.406: v94,51.34
  Bottom 0.813: v94,51.34 JP3.3
TMS  (via drill 0.8)
  Top 0.406: ATMEGA128.56 96.58,45.74 | 96.58,45.74 96.61,45.74 | 96.58,45.74 96.61,49.45 v96.11,49.45 96.08,49.45
  Bottom 0.406: 96.5,55.74 96.53,55.64 JP3.5
  Bottom 0.813: v96.11,49.45 96.5,49.24 96.5,55.74
TX0  (via drill 0.8)
  Top 0.406: 53.23,70.14 53.2,70.14
  Top 0.813: L1.2 53.23,70.14 | 53.2,70.14 C31.1 | v71.38,83.39 51.51,83.39 v51.51,80.14
  Bottom 0.406: 53.3,70.06 53.3,70.05 | 53.3,80.11 53.3,80.09 53.33,80.09 53.33,80.14 | R19.1 71.44,77.14 71.39,77.14 | v71.38,83.39 v71.39,83.39
  Bottom 0.813: L1.2 53.3,70.06 53.3,80.09 | 53.3,80.11 U$3.TX0 | 71.39,77.14 R18.2 v71.39,83.39 | 53.33,80.14 v51.51,80.14
TX+
  Bottom 0.406: U1.17 59.61,58.45 | U1.17 | 59.51,58.45 U1.17 | 66.49,77.14 66.5,77.11 66.44,77.11
  Bottom 0.61: 63.3,56.05 63.3,61.45
  Bottom 0.813: U$3.TX+ 66.49,77.14 66.49,61.45 63.3,61.45 | 63.3,56.05 59.51,56.05 59.51,58.45 | 66.5,77.11 R19.2
TX-
  Bottom 0.406: U1.16 62.09,58.34 62.11,58.34 62.2,58.34 | 68.54,79.94 68.61,79.94 | 68.54,79.94 R18.1 | 68.5,79.94 68.54,79.94
  Bottom 0.61: U$3.TX- 64.74,82.05
  Bottom 0.813: U$3.TX- 64.74,62.64 62.11,62.64 62.11,58.34 | 64.74,82.05 68.5,82.05 68.5,79.94
TXD0
  Top 0.406: ATMEGA128.3 86.62,40.77 86.01,40.16
  Top 0.813: U2.10 79.11,69.44 74.31,69.44 74.31,40.77 74.29,40.16 86.01,40.16
TXD1
  Top 0.406: ATMEGA128.28 98.97,23.9 99.95,22.81 | FT232RL.5 146.34,79.19 146.34,75.28
  Top 0.61: 147.85,73.77 146.34,75.28
  Top 0.813: 146.91,17.74 146.91,17.75 146.9,17.75 | 99.95,22.81 99.95,17.75 146.9,17.75 | 147.85,73.77 147.85,17.75 146.9,17.75
VBUS
  Top 0.254: LED3.A 123.75,78.55 123.7,78.55
  Top 0.406: C25.+ 123.75,82.28 123.75,82.38 123.75,82.44
  Top 0.813: 123.75,82.38 R8.1 | 123.75,78.55 123.75,82.28
  Bottom 0.406: 123.72,82.34 123.7,82.34 | C25.+ 123.72,82.34 | 123.72,82.34 123.75,82.34
  Bottom 0.813: 123.75,82.34 X2.VBUS
(copper drawn outside any net)
  shapes: Route2 area x48

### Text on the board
Top: 08010601 T01
Bottom: 08010601 B16
tNames: USB-B | MAC: 00-50-8D-FD-E5-16 | Pendel | + | - | + | + | LCD-Kontrast | 06.01.2008 | Ethernet Anbindung Foucaultsches Pendel | Westsächsische Hochschule Zwickau (FH) | 08010601 tN25
bNames: Ethernet Anbindung Foucaultsches Pendel | Westsächsische Hochschule Zwickau (FH) | 06.01.2008 | 08010601 bN26
tStop: 08010201 tStop29
bStop: 08010201 bStop30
